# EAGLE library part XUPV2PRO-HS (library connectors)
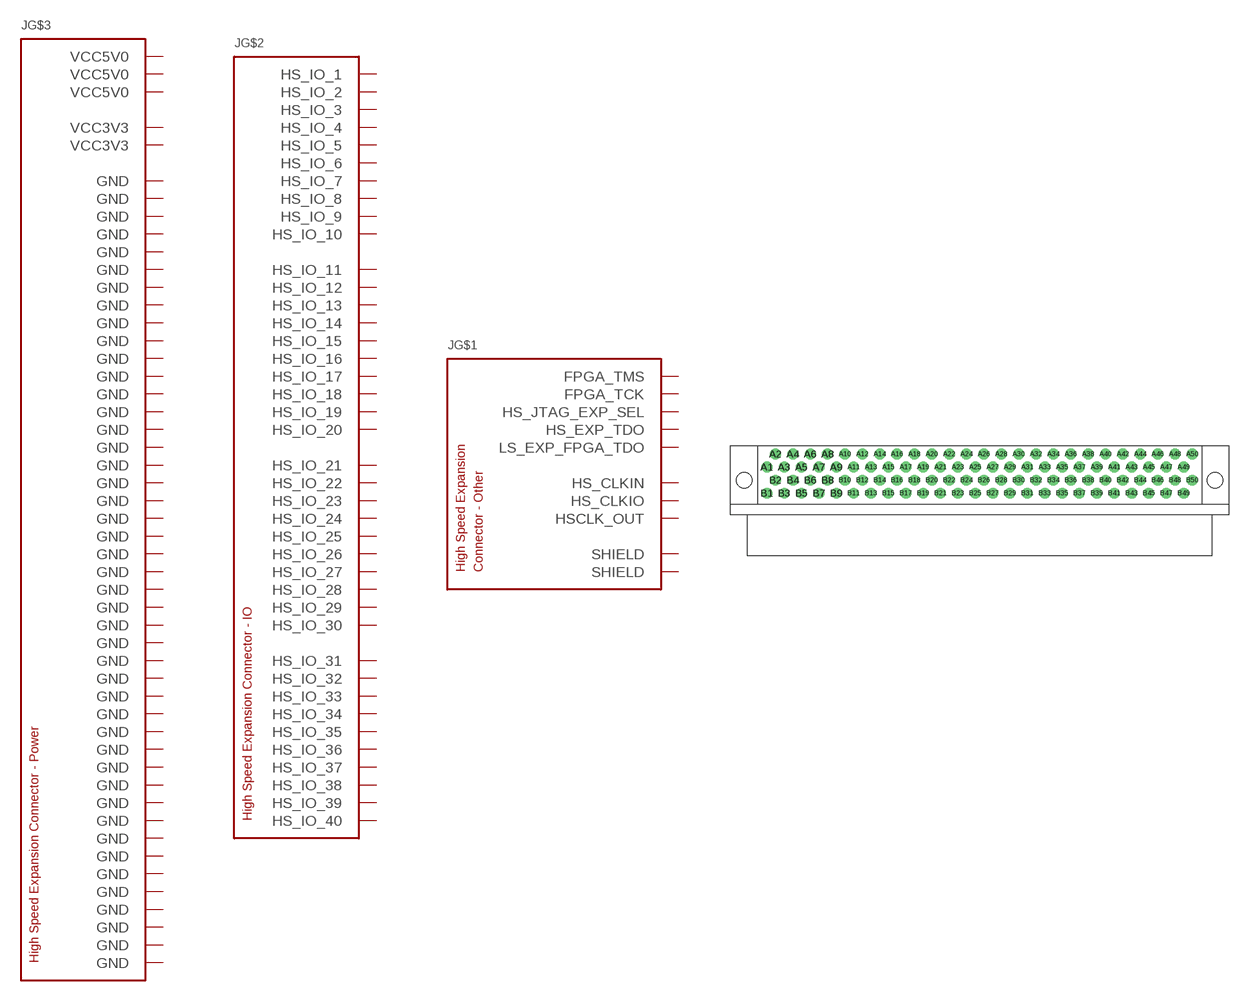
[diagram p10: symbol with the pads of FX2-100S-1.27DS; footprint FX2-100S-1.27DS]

Designator prefix J; gates G$1=XUP2VPRO-HS-OTHER G$2=XUPV2PRO-HS-IO G$3=XUPV2PRO-HS-PWR

## XUPV2PRO-HS  [FX2-100S-1.27DS]
A1  G$3:VCC3V3  pwr
A2  G$3:VCC3V3  pwr
A3  G$1:FPGA_TMS  pwr
A4  G$1:HS_JTAG_EXP_SEL  pwr
A5  G$1:HS_EXP_TDO  pwr
A6  G$2:HS_IO_1
A7  G$2:HS_IO_2
A8  G$2:HS_IO_3
A9  G$2:HS_IO_4
A10  G$2:HS_IO_5
A11  G$2:HS_IO_6
A12  G$2:HS_IO_7
A13  G$2:HS_IO_8
A14  G$2:HS_IO_9
A15  G$2:HS_IO_10
A16  G$2:HS_IO_11
A17  G$2:HS_IO_12
A18  G$2:HS_IO_13
A19  G$2:HS_IO_14
A20  G$2:HS_IO_15
A21  G$2:HS_IO_16
A22  G$2:HS_IO_17
A23  G$2:HS_IO_18
A24  G$2:HS_IO_19
A25  G$2:HS_IO_20
A26  G$2:HS_IO_21
A27  G$2:HS_IO_22
A28  G$2:HS_IO_23
A29  G$2:HS_IO_24
A30  G$2:HS_IO_25
A31  G$2:HS_IO_26
A32  G$2:HS_IO_27
A33  G$2:HS_IO_28
A34  G$2:HS_IO_29
A35  G$2:HS_IO_30
A36  G$2:HS_IO_31
A37  G$2:HS_IO_32
A38  G$2:HS_IO_33
A39  G$2:HS_IO_34
A40  G$2:HS_IO_35
A41  G$2:HS_IO_36
A42  G$2:HS_IO_37
A43  G$2:HS_IO_38
A44  G$2:HS_IO_39
A45  G$2:HS_IO_40
A46  G$3:GND  pwr
A47  G$1:HSCLK_OUT  pwr
A48  G$3:GND  pwr
A49  G$3:VCC5V0  pwr
A50  G$3:VCC5V0  pwr
B1  G$1:SHIELD  pwr
B2  G$3:GND  pwr
B3  G$1:LS_EXP_FPGA_TDO  pwr
B4  G$1:FPGA_TCK  pwr
B5  G$3:GND  pwr
B6  G$3:GND  pwr
B7  G$3:GND  pwr
B8  G$3:GND  pwr
B9  G$3:GND  pwr
B10  G$3:GND  pwr
B11  G$3:GND  pwr
B12  G$3:GND  pwr
B13  G$3:GND  pwr
B14  G$3:GND  pwr
B15  G$3:GND  pwr
B16  G$3:GND  pwr
B17  G$3:GND  pwr
B18  G$3:GND  pwr
B19  G$3:GND  pwr
B20  G$3:GND  pwr
B21  G$3:GND  pwr
B22  G$3:GND  pwr
B23  G$3:GND  pwr
B24  G$3:GND  pwr
B25  G$3:GND  pwr
B26  G$3:GND  pwr
B27  G$3:GND  pwr
B28  G$3:GND  pwr
B29  G$3:GND  pwr
B30  G$3:GND  pwr
B31  G$3:GND  pwr
B32  G$3:GND  pwr
B33  G$3:GND  pwr
B34  G$3:GND  pwr
B35  G$3:GND  pwr
B36  G$3:GND  pwr
B37  G$3:GND  pwr
B38  G$3:GND  pwr
B39  G$3:GND  pwr
B40  G$3:GND  pwr
B41  G$3:GND  pwr
B42  G$3:GND  pwr
B43  G$3:GND  pwr
B44  G$3:GND  pwr
B45  G$3:GND  pwr
B46  G$1:HS_CLKIN  pwr
B47  G$3:GND  pwr
B48  G$1:HS_CLKIO  pwr
B49  G$3:VCC5V0  pwr
B50  G$1:SHIELD  pwr

## Footprint FX2-100S-1.27DS (pad centres in mm)
drill 0.85 pad 1.6 round: A1 -31.115,1.905; A2 -29.845,3.81; A3 -28.575,1.905; A4 -27.305,3.81; A5 -26.035,1.905; A6 -24.765,3.81; A7 -23.495,1.905; A8 -22.225,3.81; A9 -20.955,1.905; A10 -19.685,3.81; A11 -18.415,1.905; A12 -17.145,3.81; A13 -15.875,1.905; A14 -14.605,3.81; A15 -13.335,1.905; A16 -12.065,3.81; A17 -10.795,1.905; A18 -9.525,3.81; A19 -8.255,1.905; A20 -6.985,3.81; A21 -5.715,1.905; A22 -4.445,3.81; A23 -3.175,1.905; A24 -1.905,3.81; A25 -0.635,1.905; A26 0.635,3.81; A27 1.905,1.905; A28 3.175,3.81; A29 4.445,1.905; A30 5.715,3.81; A31 6.985,1.905; A32 8.255,3.81; A33 9.525,1.905; A34 10.795,3.81; A35 12.065,1.905; A36 13.335,3.81; A37 14.605,1.905; A38 15.875,3.81; A39 17.145,1.905; A40 18.415,3.81; A41 19.685,1.905; A42 20.955,3.81; A43 22.225,1.905; A44 23.495,3.81; A45 24.765,1.905; A46 26.035,3.81; A47 27.305,1.905; A48 28.575,3.81; A49 29.845,1.905; A50 31.115,3.81; B1 -31.115,-1.905; B2 -29.845,0; B3 -28.575,-1.905; B4 -27.305,0; B5 -26.035,-1.905; B6 -24.765,0; B7 -23.495,-1.905; B8 -22.225,0; B9 -20.955,-1.905; B10 -19.685,0; B11 -18.415,-1.905; B12 -17.145,0; B13 -15.875,-1.905; B14 -14.605,0; B15 -13.335,-1.905; B16 -12.065,0; B17 -10.795,-1.905; B18 -9.525,0; B19 -8.255,-1.905; B20 -6.985,0; B21 -5.715,-1.905; B22 -4.445,0; B23 -3.175,-1.905; B24 -1.905,0; B25 -0.635,-1.905; B26 0.635,0; B27 1.905,-1.905; B28 3.175,0; B29 4.445,-1.905; B30 5.715,0; B31 6.985,-1.905; B32 8.255,0; B33 9.525,-1.905; B34 10.795,0; B35 12.065,-1.905; B36 13.335,0; B37 14.605,-1.905; B38 15.875,0; B39 17.145,-1.905; B40 18.415,0; B41 19.685,-1.905; B42 20.955,0; B43 22.225,-1.905; B44 23.495,0; B45 24.765,-1.905; B46 26.035,0; B47 27.305,-1.905; B48 28.575,0; B49 29.845,-1.905; B50 31.115,0
hole 2.25 at -34.425,0
hole 2.25 at 34.425,0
